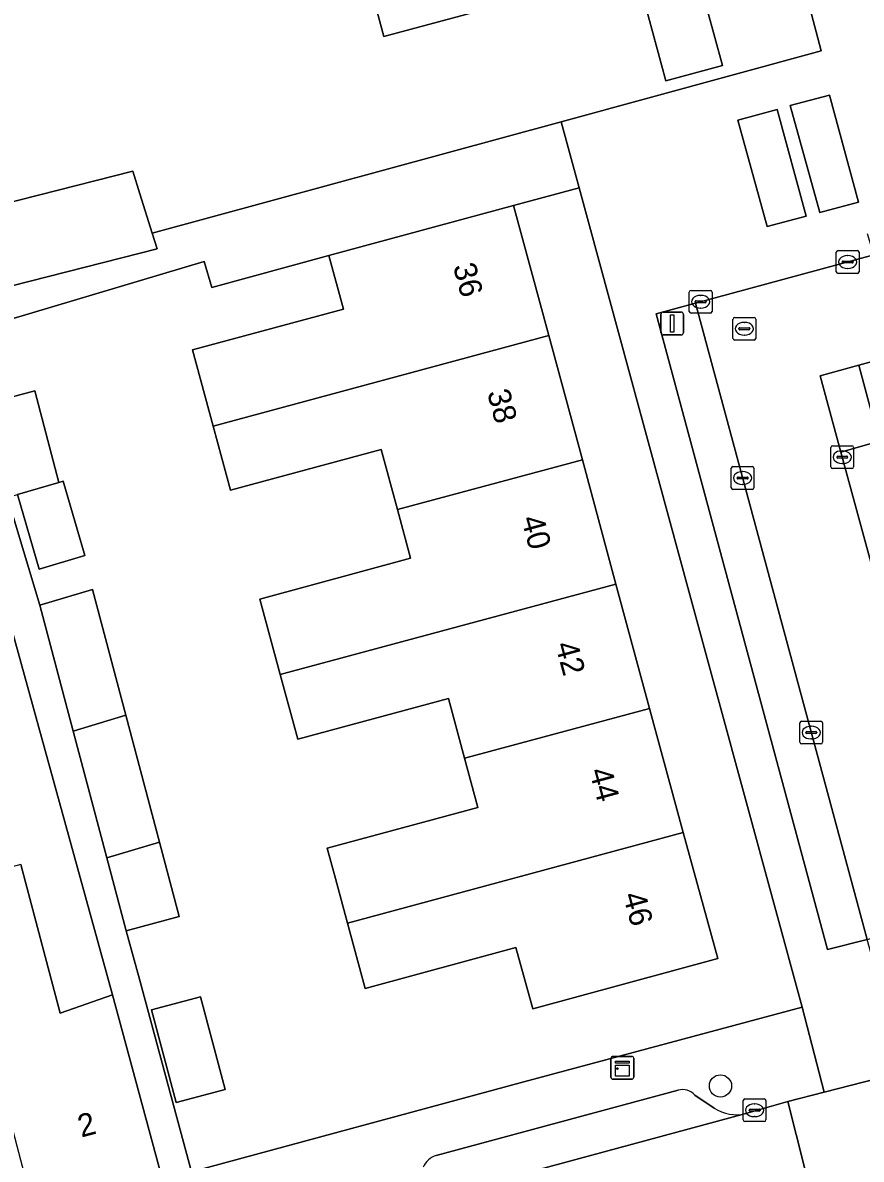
# Model space of a CAD drawing. Extents: x 159262 to 160143, y 383399 to 384319.
# Drawn here: x 159776.11 to 159813.01, y 383819.59 to 383869.58 of the extents above; entities that cross this region are included whole.
import ezdxf

# ---------------------------------------------------------------- set-up
doc = ezdxf.new("R2010")
doc.units = 0
for name, color, linetype in [('IMGEO_Boom', 7, 'Continuous'), ('IMGEO_Erf', 7, 'Continuous'), ('IMGEO_Kast', 7, 'Continuous'), ('IMGEO_Kolk', 7, 'Continuous'), ('IMGEO_Lichtmast', 7, 'Continuous'), ('IMGEO_Pand', 7, 'Continuous'), ('IMGEO_Pand_nummerreeks', 7, 'Continuous'), ('IMGEO_Parkeervlak_open', 7, 'Continuous'), ('IMGEO_Rijbaan_lokaal_open', 7, 'Continuous'), ('IMGEO_Rioolput', 7, 'Continuous'), ('IMGEO_Voetpad_open', 7, 'Continuous')]:
    doc.layers.add(name, color=color, linetype=linetype)

msp = doc.modelspace()

# ---------------------------------------------------------------- linework, layer by layer
at = {"layer": 'IMGEO_Boom'}
msp.add_circle((159806.814, 383822.819), 0.489, dxfattribs=at)
at = {"layer": 'IMGEO_Erf'}
for points in [[(159772.634, 383860.939), (159780.947, 383863.051), (159781.261, 383862.057), (159781.807, 383860.328), (159799.81, 383865.219), (159811.247, 383868.349), (159809.752, 383874.036)], [(159798.61, 383870.762), (159791.999, 383868.973), (159790.981, 383872.738)], [(159805.561, 383872.643), (159806.898, 383867.702), (159804.407, 383867.028), (159803.07, 383871.969)], [(159775.439, 383848.705), (159776.858, 383843.958), (159779.18, 383844.649), (159780.648, 383839.118), (159782.129, 383833.534), (159782.994, 383830.275), (159780.656, 383829.644), (159781.244, 383827.509), (159783.539, 383819.032), (159798.168, 383822.992), (159810.41, 383826.285), (159805.418, 383844.577), (159800.596, 383862.326), (159797.711, 383861.542), (159799.258, 383855.824), (159800.736, 383850.358), (159802.214, 383844.891), (159803.693, 383839.425), (159805.171, 383833.96), (159806.695, 383828.427), (159798.556, 383826.211), (159797.807, 383828.902), (159791.175, 383827.108), (159790.399, 383829.977), (159789.87, 383831.935), (159789.507, 383833.277), (159796.139, 383835.071), (159795.555, 383837.231), (159794.844, 383839.859), (159788.212, 383838.065), (159787.443, 383840.91), (159786.544, 383844.233), (159793.176, 383846.027), (159792.598, 383848.164), (159791.881, 383850.815), (159785.249, 383849.021), (159784.486, 383851.842), (159783.58, 383855.189), (159790.222, 383856.985), (159789.586, 383859.336), (159784.427, 383857.935), (159784.089, 383859.072), (159773.554, 383855.94)], [(159774.374, 383852.793), (159776.644, 383853.384), (159777.691, 383849.363), (159777.886, 383849.42), (159778.844, 383846.141), (159776.832, 383845.553), (159775.873, 383848.832)], [(159776.017, 383832.553), (159777.749, 383826.021), (159780.061, 383826.825), (159773.045, 383852.196)]]:
    msp.add_lwpolyline(points, dxfattribs=at)
msp.add_lwpolyline([(159783.934, 383826.735), (159785.016, 383822.658), (159782.859, 383822.086), (159781.777, 383826.162)], close=True, dxfattribs=at)
at = {"layer": 'IMGEO_Kast'}
for p, q in [((159801.997, 383823.193), (159801.997, 383824.034)), ((159801.997, 383824.034), (159801.997, 383823.193)), ((159802.072, 383824.118), (159802.913, 383824.118)), ((159802.913, 383824.118), (159802.072, 383824.118)), ((159802.997, 383824.043), (159802.997, 383823.202)), ((159802.997, 383823.202), (159802.997, 383824.043)), ((159802.922, 383823.118), (159802.081, 383823.118)), ((159802.081, 383823.118), (159802.922, 383823.118))]:
    msp.add_line(p, q, dxfattribs=at)
for points in [[(159802.192, 383823.908), (159802.792, 383823.908), (159802.792, 383823.823), (159802.192, 383823.823), (159802.192, 383823.908)], [(159802.192, 383823.733), (159802.792, 383823.733), (159802.792, 383823.244), (159802.192, 383823.244), (159802.192, 383823.733)]]:
    msp.add_lwpolyline(points, dxfattribs=at)
msp.add_circle((159802.276, 383823.582), 0.0377, dxfattribs=at)
for centre, start, end in [((159802.075, 383824.04), 92.4484, 184.2845), ((159802.075, 383824.04), 92.4484, 184.2845), ((159802.919, 383824.04), 2.4484, 94.2845), ((159802.919, 383824.04), 2.4484, 94.2845), ((159802.075, 383823.196), 182.4484, 274.2845), ((159802.075, 383823.196), 182.4484, 274.2845), ((159802.919, 383823.196), 272.4484, 4.2845), ((159802.919, 383823.196), 272.4484, 4.2845)]:
    msp.add_arc(centre, 0.0779, start, end, dxfattribs=at)
at = {"layer": 'IMGEO_Kolk'}
for p, q in [((159811.913, 383858.631), (159811.913, 383859.483)), ((159811.988, 383859.557), (159812.84, 383859.557)), ((159812.401, 383859.337), (159812.426, 383859.337)), ((159812.914, 383859.483), (159812.914, 383858.631)), ((159812.172, 383859.051), (159812.172, 383859.063)), ((159812.61, 383859.014), (159812.212, 383859.014)), ((159812.215, 383859.1), (159812.613, 383859.1)), ((159812.424, 383858.777), (159812.399, 383858.777)), ((159812.656, 383859.063), (159812.656, 383859.051)), ((159812.84, 383858.557), (159811.988, 383858.557)), ((159805.444, 383856.883), (159805.444, 383857.735)), ((159805.519, 383857.809), (159806.371, 383857.809)), ((159806.445, 383857.735), (159806.445, 383856.883)), ((159805.703, 383857.303), (159805.703, 383857.315)), ((159806.141, 383857.266), (159805.743, 383857.266)), ((159805.746, 383857.352), (159806.144, 383857.352)), ((159805.932, 383857.589), (159805.957, 383857.589)), ((159806.187, 383857.315), (159806.187, 383857.303)), ((159806.371, 383856.809), (159805.519, 383856.809)), ((159805.955, 383857.029), (159805.93, 383857.029)), ((159811.673, 383850.046), (159811.673, 383850.898)), ((159811.748, 383850.972), (159812.6, 383850.972)), ((159812.161, 383850.752), (159812.186, 383850.752)), ((159812.674, 383850.898), (159812.674, 383850.046)), ((159811.932, 383850.466), (159811.932, 383850.478)), ((159812.37, 383850.429), (159811.972, 383850.429)), ((159811.975, 383850.515), (159812.373, 383850.515)), ((159812.416, 383850.478), (159812.416, 383850.466)), ((159807.287, 383849.131), (159807.287, 383849.983)), ((159807.362, 383850.057), (159808.214, 383850.057)), ((159807.775, 383849.837), (159807.8, 383849.837)), ((159808.288, 383849.983), (159808.288, 383849.131)), ((159812.6, 383849.972), (159811.748, 383849.972)), ((159812.184, 383850.192), (159812.159, 383850.192)), ((159807.546, 383849.551), (159807.546, 383849.563)), ((159807.984, 383849.514), (159807.586, 383849.514)), ((159807.589, 383849.6), (159807.987, 383849.6)), ((159807.798, 383849.277), (159807.773, 383849.277)), ((159808.03, 383849.563), (159808.03, 383849.551)), ((159808.214, 383849.057), (159807.362, 383849.057)), ((159810.309, 383837.935), (159810.309, 383838.787)), ((159810.384, 383838.861), (159811.236, 383838.861)), ((159811.31, 383838.787), (159811.31, 383837.935)), ((159810.568, 383838.355), (159810.568, 383838.367)), ((159811.006, 383838.318), (159810.608, 383838.318)), ((159810.611, 383838.404), (159811.009, 383838.404)), ((159810.797, 383838.641), (159810.822, 383838.641)), ((159811.052, 383838.367), (159811.052, 383838.355)), ((159811.236, 383837.861), (159810.384, 383837.861)), ((159810.82, 383838.081), (159810.795, 383838.081)), ((159807.89, 383822.249), (159808.742, 383822.249)), ((159807.815, 383821.323), (159807.815, 383822.175)), ((159808.074, 383821.743), (159808.074, 383821.755)), ((159808.117, 383821.792), (159808.515, 383821.792)), ((159808.303, 383822.029), (159808.328, 383822.029)), ((159808.558, 383821.755), (159808.558, 383821.743)), ((159808.816, 383822.175), (159808.816, 383821.323)), ((159808.742, 383821.249), (159807.89, 383821.249)), ((159808.512, 383821.706), (159808.114, 383821.706)), ((159808.326, 383821.469), (159808.301, 383821.469))]:
    msp.add_line(p, q, dxfattribs=at)
for points in [[(159811.913, 383858.631), (159811.913, 383859.483)], [(159811.988, 383859.557), (159812.84, 383859.557)], [(159812.914, 383859.483), (159812.914, 383858.631)], [(159812.84, 383858.557), (159811.988, 383858.557)], [(159805.444, 383856.883), (159805.444, 383857.735)], [(159805.519, 383857.809), (159806.371, 383857.809)], [(159806.445, 383857.735), (159806.445, 383856.883)], [(159806.371, 383856.809), (159805.519, 383856.809)], [(159811.673, 383850.046), (159811.673, 383850.898)], [(159811.748, 383850.972), (159812.6, 383850.972)], [(159812.674, 383850.898), (159812.674, 383850.046)], [(159807.287, 383849.131), (159807.287, 383849.983)], [(159807.362, 383850.057), (159808.214, 383850.057)], [(159808.288, 383849.983), (159808.288, 383849.131)], [(159812.6, 383849.972), (159811.748, 383849.972)], [(159808.214, 383849.057), (159807.362, 383849.057)], [(159810.309, 383837.935), (159810.309, 383838.787)], [(159810.384, 383838.861), (159811.236, 383838.861)], [(159811.31, 383838.787), (159811.31, 383837.935)], [(159811.236, 383837.861), (159810.384, 383837.861)], [(159807.89, 383822.249), (159808.742, 383822.249)], [(159807.815, 383821.323), (159807.815, 383822.175)], [(159808.816, 383822.175), (159808.816, 383821.323)], [(159808.742, 383821.249), (159807.89, 383821.249)]]:
    msp.add_lwpolyline(points, dxfattribs=at)
for centre, radius, start, end in [((159811.99, 383859.481), 0.0765, 91.552, 178.448), ((159811.99, 383859.481), 0.0765, 91.552, 178.448), ((159812.838, 383859.481), 0.0765, 1.552, 88.448), ((159812.838, 383859.481), 0.0765, 1.552, 88.448), ((159812.212, 383859.06), 0.0403, 85.8775, 175.7526), ((159812.209, 383859.05), 0.0366, 178.938, 274.7102), ((159812.613, 383859.057), 0.043, 264.8664, 352.4533), ((159812.617, 383859.062), 0.0386, 1.7309, 96.639), ((159811.99, 383858.633), 0.0765, 181.552, 268.448), ((159811.99, 383858.633), 0.0765, 181.552, 268.448), ((159812.838, 383858.633), 0.0765, 271.552, 358.448), ((159812.838, 383858.633), 0.0765, 271.552, 358.448), ((159805.521, 383857.733), 0.0765, 91.552, 178.448), ((159805.521, 383857.733), 0.0765, 91.552, 178.448), ((159806.369, 383857.733), 0.0765, 1.552, 88.448), ((159806.369, 383857.733), 0.0765, 1.552, 88.448), ((159805.743, 383857.312), 0.0403, 85.8775, 175.7526), ((159805.74, 383857.302), 0.0366, 178.938, 274.7102), ((159806.144, 383857.309), 0.043, 264.8664, 352.4533), ((159806.148, 383857.314), 0.0386, 1.7309, 96.639), ((159805.521, 383856.885), 0.0765, 181.552, 268.448), ((159805.521, 383856.885), 0.0765, 181.552, 268.448), ((159806.369, 383856.885), 0.0765, 271.552, 358.448), ((159806.369, 383856.885), 0.0765, 271.552, 358.448), ((159811.75, 383850.896), 0.0765, 91.552, 178.448), ((159811.75, 383850.896), 0.0765, 91.552, 178.448), ((159812.598, 383850.896), 0.0765, 1.552, 88.448), ((159812.598, 383850.896), 0.0765, 1.552, 88.448), ((159811.972, 383850.475), 0.0403, 85.8775, 175.7526), ((159811.969, 383850.465), 0.0366, 178.938, 274.7102), ((159812.373, 383850.472), 0.043, 264.8664, 352.4533), ((159812.377, 383850.477), 0.0386, 1.7309, 96.639), ((159807.364, 383849.981), 0.0765, 91.552, 178.448), ((159807.364, 383849.981), 0.0765, 91.552, 178.448), ((159808.212, 383849.981), 0.0765, 1.552, 88.448), ((159808.212, 383849.981), 0.0765, 1.552, 88.448), ((159811.75, 383850.048), 0.0765, 181.552, 268.448), ((159811.75, 383850.048), 0.0765, 181.552, 268.448), ((159812.598, 383850.048), 0.0765, 271.552, 358.448), ((159812.598, 383850.048), 0.0765, 271.552, 358.448), ((159807.586, 383849.56), 0.0403, 85.8775, 175.7526), ((159807.583, 383849.55), 0.0366, 178.938, 274.7102), ((159807.987, 383849.557), 0.043, 264.8664, 352.4533), ((159807.991, 383849.562), 0.0386, 1.7309, 96.639), ((159807.364, 383849.133), 0.0765, 181.552, 268.448), ((159807.364, 383849.133), 0.0765, 181.552, 268.448), ((159808.212, 383849.133), 0.0765, 271.552, 358.448), ((159808.212, 383849.133), 0.0765, 271.552, 358.448), ((159810.386, 383838.785), 0.0765, 91.552, 178.448), ((159810.386, 383838.785), 0.0765, 91.552, 178.448), ((159811.234, 383838.785), 0.0765, 1.552, 88.448), ((159811.234, 383838.785), 0.0765, 1.552, 88.448), ((159810.608, 383838.364), 0.0403, 85.8775, 175.7526), ((159810.605, 383838.354), 0.0366, 178.938, 274.7102), ((159811.009, 383838.361), 0.043, 264.8664, 352.4533), ((159811.013, 383838.366), 0.0386, 1.7309, 96.639), ((159810.386, 383837.937), 0.0765, 181.552, 268.448), ((159810.386, 383837.937), 0.0765, 181.552, 268.448), ((159811.234, 383837.937), 0.0765, 271.552, 358.448), ((159811.234, 383837.937), 0.0765, 271.552, 358.448), ((159807.892, 383822.173), 0.0765, 91.552, 178.448), ((159807.892, 383822.173), 0.0765, 91.552, 178.448), ((159808.74, 383822.173), 0.0765, 1.552, 88.448), ((159808.74, 383822.173), 0.0765, 1.552, 88.448), ((159808.114, 383821.752), 0.0403, 85.8775, 175.7526), ((159808.111, 383821.742), 0.0366, 178.938, 274.7102), ((159808.515, 383821.749), 0.043, 264.8664, 352.4533), ((159808.519, 383821.754), 0.0386, 1.7309, 96.639), ((159807.892, 383821.325), 0.0765, 181.552, 268.448), ((159807.892, 383821.325), 0.0765, 181.552, 268.448), ((159808.74, 383821.325), 0.0765, 271.552, 358.448), ((159808.74, 383821.325), 0.0765, 271.552, 358.448)]:
    msp.add_arc(centre, radius, start, end, dxfattribs=at)
for centre, major_axis, ratio, start_param, end_param in [((159812.4, 383859.057), (-0.387, 0.002), 0.722429, 4.712389, 7.853982), ((159812.425, 383859.057), (-0.39, 0.002), 0.717154, 1.570796, 4.712389), ((159805.931, 383857.309), (-0.387, 0.002), 0.722429, 4.712389, 7.853982), ((159805.956, 383857.309), (-0.39, 0.002), 0.717154, 1.570796, 4.712389), ((159812.16, 383850.472), (-0.387, 0.002), 0.722429, 4.712389, 7.853982), ((159812.185, 383850.472), (-0.39, 0.002), 0.717154, 1.570796, 4.712389), ((159807.774, 383849.557), (-0.387, 0.002), 0.722429, 4.712389, 7.853982), ((159807.799, 383849.557), (-0.39, 0.002), 0.717154, 1.570796, 4.712389), ((159810.796, 383838.361), (-0.387, 0.002), 0.722429, 4.712389, 7.853982), ((159810.821, 383838.361), (-0.39, 0.002), 0.717154, 1.570796, 4.712389), ((159808.302, 383821.749), (-0.387, 0.002), 0.722429, 4.712389, 7.853982), ((159808.327, 383821.749), (-0.39, 0.002), 0.717154, 1.570796, 4.712389)]:
    msp.add_ellipse(centre, major_axis=major_axis, ratio=ratio, start_param=start_param, end_param=end_param, dxfattribs=at)
at = {"layer": 'IMGEO_Lichtmast'}
for p, q in [((159804.196, 383855.951), (159804.196, 383856.751)), ((159804.196, 383856.751), (159804.196, 383855.951)), ((159804.296, 383856.851), (159805.086, 383856.851)), ((159805.086, 383856.851), (159804.296, 383856.851)), ((159805.186, 383856.751), (159805.186, 383855.951)), ((159805.186, 383855.951), (159805.186, 383856.751)), ((159805.086, 383855.851), (159804.296, 383855.851)), ((159804.296, 383855.851), (159805.086, 383855.851))]:
    msp.add_line(p, q, dxfattribs=at)
msp.add_lwpolyline([(159804.616, 383856.726), (159804.766, 383856.726), (159804.766, 383855.976), (159804.616, 383855.976), (159804.616, 383856.726)], dxfattribs=at)
for centre, start, end in [((159804.296, 383856.751), 90, 180), ((159804.296, 383856.751), 90, 180), ((159805.086, 383856.751), 0, 90), ((159805.086, 383856.751), 360, 90), ((159804.296, 383855.951), 180, 270), ((159804.296, 383855.951), 180, 270), ((159805.086, 383855.951), 270, 0), ((159805.086, 383855.951), 270, 0)]:
    msp.add_arc(centre, 0.1, start, end, dxfattribs=at)
at = {"layer": 'IMGEO_Pand'}
for points in [[(159805.237, 383878.887), (159797.395, 383876.768), (159796.897, 383876.634), (159797.476, 383874.493), (159790.981, 383872.738), (159791.999, 383868.973), (159798.61, 383870.762), (159803.07, 383871.969), (159805.561, 383872.643), (159807.036, 383873.042), (159806.897, 383873.554), (159806.685, 383873.496)], [(159805.561, 383872.643), (159803.07, 383871.969), (159804.407, 383867.028), (159806.898, 383867.702)], [(159773.026, 383869.247), (159766.711, 383867.668), (159768.227, 383862.468), (159769.29, 383860.847), (159774.002, 383857.6), (159782.025, 383859.638), (159781.807, 383860.328), (159781.261, 383862.057), (159780.947, 383863.051), (159772.634, 383860.939), (159771.931, 383863.67), (159774.305, 383864.282)], [(159797.711, 383861.542), (159789.586, 383859.336), (159790.222, 383856.985), (159783.58, 383855.189), (159784.486, 383851.842), (159799.258, 383855.824)], [(159799.258, 383855.824), (159784.486, 383851.842), (159785.249, 383849.021), (159791.881, 383850.815), (159792.598, 383848.164), (159800.736, 383850.358)], [(159776.644, 383853.384), (159774.374, 383852.793), (159775.439, 383848.705), (159775.873, 383848.832), (159777.691, 383849.363)], [(159802.214, 383844.891), (159800.736, 383850.358), (159792.598, 383848.164), (159793.176, 383846.027), (159786.544, 383844.233), (159787.443, 383840.91), (159787.603, 383840.953)], [(159777.886, 383849.42), (159777.691, 383849.363), (159775.873, 383848.832), (159776.832, 383845.553), (159778.844, 383846.141)], [(159802.214, 383844.891), (159787.603, 383840.953), (159787.443, 383840.91), (159788.212, 383838.065), (159794.844, 383839.859), (159795.555, 383837.231), (159795.673, 383837.263), (159803.693, 383839.425)], [(159778.325, 383838.427), (159780.648, 383839.118), (159779.18, 383844.649), (159776.858, 383843.958)], [(159790.399, 383829.977), (159805.171, 383833.96), (159803.693, 383839.425), (159795.673, 383837.263), (159795.555, 383837.231), (159796.139, 383835.071), (159789.507, 383833.277), (159789.87, 383831.935)], [(159780.648, 383839.118), (159778.325, 383838.427), (159779.807, 383832.844), (159782.129, 383833.534)], [(159790.399, 383829.977), (159791.175, 383827.108), (159797.807, 383828.902), (159798.556, 383826.211), (159806.695, 383828.427), (159805.171, 383833.96)], [(159782.129, 383833.534), (159779.807, 383832.844), (159780.656, 383829.644), (159782.994, 383830.275)], [(159780.061, 383826.825), (159777.749, 383826.021), (159776.017, 383832.553), (159775.641, 383832.453), (159772.809, 383831.702), (159776.639, 383817.16), (159782.255, 383818.684)], [(159781.777, 383826.162), (159782.859, 383822.086), (159785.016, 383822.658), (159783.934, 383826.735)]]:
    msp.add_lwpolyline(points, close=True, dxfattribs=at)
at = {"layer": 'IMGEO_Parkeervlak_open'}
for points in [[(159811.189, 383861.229), (159812.893, 383861.69), (159811.616, 383866.39), (159809.887, 383865.939)], [(159808.868, 383860.619), (159810.584, 383861.067), (159809.315, 383865.765), (159807.582, 383865.302)], [(159805.711, 383857.248), (159803.983, 383856.776), (159811.53, 383828.823), (159813.268, 383829.254)], [(159812.114, 383850.695), (159813.801, 383851.172), (159812.897, 383854.513), (159811.2, 383854.049)], [(159812.114, 383850.695), (159815.601, 383837.899), (159817.266, 383838.369), (159813.801, 383851.172)]]:
    msp.add_lwpolyline(points, close=True, dxfattribs=at)
for points in [[(159804.957, 383822.627), (159794.306, 383819.764)], [(159806.541, 383821.844), (159805.684, 383822.406)], [(159779.954, 383814.038), (159807.933, 383821.6)]]:
    msp.add_lwpolyline(points, dxfattribs=at)
for centre, radius, start, end in [((159805.159, 383821.986), 0.672, 38.6735, 107.5091), ((159807.521, 383823.344), 1.792, 236.8387, 283.2768), ((159794.618, 383818.834), 0.981, 108.578, 155.5055)]:
    msp.add_arc(centre, radius, start, end, dxfattribs=at)
at = {"layer": 'IMGEO_Rijbaan_lokaal_open'}
for points in [[(159812.114, 383850.695), (159811.2, 383854.049), (159812.897, 383854.513), (159827.025, 383858.376), (159825.844, 383862.726), (159821.446, 383861.508), (159820.087, 383866.52), (159819.812, 383867.366), (159816.206, 383866.393), (159816.455, 383865.576), (159817.836, 383860.538), (159813.56, 383859.369), (159805.711, 383857.248), (159813.268, 383829.254), (159817.626, 383830.468), (159815.601, 383837.899)], [(159818.156, 383828.416), (159813.846, 383827.217), (159814.865, 383823.438), (159811.373, 383822.538), (159809.783, 383822.128), (159810.888, 383817.723), (159812.514, 383818.172), (159816.064, 383819.153), (159817.391, 383814.24), (159820.841, 383815.179), (159820.687, 383815.791), (159821.45, 383816.037), (159821.238, 383816.833)], [(159807.933, 383821.6), (159779.954, 383814.038), (159781.118, 383809.691), (159808.996, 383817.216), (159810.888, 383817.723), (159809.783, 383822.128)]]:
    msp.add_lwpolyline(points, close=True, dxfattribs=at)
at = {"layer": 'IMGEO_Rioolput'}
for p, q in [((159807.366, 383855.696), (159807.366, 383856.548)), ((159807.441, 383856.622), (159808.293, 383856.622)), ((159807.854, 383856.402), (159807.879, 383856.402)), ((159808.367, 383856.548), (159808.367, 383855.696)), ((159807.625, 383856.116), (159807.625, 383856.128)), ((159808.063, 383856.079), (159807.665, 383856.079)), ((159807.668, 383856.165), (159808.066, 383856.165)), ((159807.877, 383855.842), (159807.852, 383855.842)), ((159808.109, 383856.128), (159808.109, 383856.116)), ((159808.293, 383855.622), (159807.441, 383855.622))]:
    msp.add_line(p, q, dxfattribs=at)
for points in [[(159807.366, 383855.696), (159807.366, 383856.548)], [(159807.441, 383856.622), (159808.293, 383856.622)], [(159808.367, 383856.548), (159808.367, 383855.696)], [(159808.293, 383855.622), (159807.441, 383855.622)]]:
    msp.add_lwpolyline(points, dxfattribs=at)
for centre, radius, start, end in [((159807.443, 383856.546), 0.0765, 91.552, 178.448), ((159807.443, 383856.546), 0.0765, 91.552, 178.448), ((159808.291, 383856.546), 0.0765, 1.552, 88.448), ((159808.291, 383856.546), 0.0765, 1.552, 88.448), ((159807.665, 383856.125), 0.0403, 85.8775, 175.7526), ((159807.662, 383856.115), 0.0366, 178.938, 274.7102), ((159808.066, 383856.122), 0.043, 264.8664, 352.4533), ((159808.07, 383856.127), 0.0386, 1.7309, 96.639), ((159807.443, 383855.698), 0.0765, 181.552, 268.448), ((159807.443, 383855.698), 0.0765, 181.552, 268.448), ((159808.291, 383855.698), 0.0765, 271.552, 358.448), ((159808.291, 383855.698), 0.0765, 271.552, 358.448)]:
    msp.add_arc(centre, radius, start, end, dxfattribs=at)
for centre, major_axis, ratio, start_param, end_param in [((159807.853, 383856.122), (-0.387, 0.002), 0.722429, 4.712389, 7.853982), ((159807.878, 383856.122), (-0.39, 0.002), 0.717154, 1.570796, 4.712389)]:
    msp.add_ellipse(centre, major_axis=major_axis, ratio=ratio, start_param=start_param, end_param=end_param, dxfattribs=at)
at = {"layer": 'IMGEO_Voetpad_open'}
for points in [[(159797.608, 383919.451), (159799.088, 383913.971), (159800.568, 383908.491), (159802.048, 383903.01), (159803.527, 383897.53), (159805.038, 383891.935), (159805.363, 383890.726), (159809.839, 383874.056), (159809.752, 383874.036), (159811.247, 383868.349), (159799.81, 383865.219), (159800.596, 383862.326), (159805.418, 383844.577), (159810.41, 383826.285), (159811.373, 383822.538), (159814.865, 383823.438), (159813.846, 383827.217), (159813.268, 383829.254), (159811.53, 383828.823), (159803.983, 383856.776), (159805.711, 383857.248), (159813.56, 383859.369), (159813.286, 383860.29)], [(159773.554, 383855.94), (159784.089, 383859.072), (159784.427, 383857.935), (159789.586, 383859.336), (159797.711, 383861.542), (159800.596, 383862.326), (159799.81, 383865.219), (159781.807, 383860.328), (159782.025, 383859.638), (159774.002, 383857.6)], [(159816.089, 383854.397), (159816.767, 383854.581), (159819.014, 383855.189), (159827.288, 383857.429), (159828.31, 383857.705), (159828.046, 383858.656), (159827.025, 383858.376), (159812.897, 383854.513), (159813.801, 383851.172), (159817.266, 383838.369), (159819.279, 383830.929), (159817.626, 383830.468), (159818.156, 383828.416), (159821.238, 383816.833), (159825.07, 383817.837), (159824.545, 383820.045), (159823.001, 383819.628), (159822.082, 383823.083), (159820.938, 383827.383)], [(159773.045, 383852.196), (159780.061, 383826.825), (159782.255, 383818.684), (159783.539, 383819.032), (159781.244, 383827.509), (159780.656, 383829.644), (159779.807, 383832.844), (159778.325, 383838.427), (159776.858, 383843.958), (159775.439, 383848.705)], [(159807.933, 383821.6), (159809.783, 383822.128), (159811.373, 383822.538), (159810.41, 383826.285), (159798.168, 383822.992), (159783.539, 383819.032), (159782.255, 383818.684), (159776.639, 383817.16), (159771.151, 383815.672), (159765.66, 383814.182), (159760.083, 383812.67), (159756.052, 383811.573), (159731.977, 383805.001), (159732.956, 383801.323)], [(159794.306, 383819.764), (159804.957, 383822.627)], [(159805.684, 383822.406), (159806.541, 383821.844)]]:
    msp.add_lwpolyline(points, dxfattribs=at)
for points in [[(159811.616, 383866.39), (159812.893, 383861.69), (159811.189, 383861.229), (159809.887, 383865.939)], [(159809.315, 383865.765), (159810.584, 383861.067), (159808.868, 383860.619), (159807.582, 383865.302)]]:
    msp.add_lwpolyline(points, close=True, dxfattribs=at)
for centre, radius, start, end in [((159805.159, 383821.986), 0.672, 38.6735, 107.5091), ((159807.521, 383823.344), 1.792, 236.8387, 283.2768), ((159794.618, 383818.834), 0.981, 108.578, 155.5055)]:
    msp.add_arc(centre, radius, start, end, dxfattribs=at)

# ---------------------------------------------------------------- texts
at = {"layer": 'IMGEO_Pand_nummerreeks'}
for s, rotation, p in [('36', 285.1201, (159795.036, 383858.87)), ('38', 285.1214, (159796.537, 383853.318)), ('40', 285.1214, (159798.036, 383847.769)), ('42', 285.1214, (159799.533, 383842.227)), ('44', 285.1214, (159801.034, 383836.675)), ('46', 285.1938, (159802.513, 383831.208)), ('2', 14.8568, (159778.683, 383820.543))]:
    msp.add_text(s, height=1, rotation=rotation, dxfattribs=at).set_placement(p)

doc.saveas('drawing.dxf')
